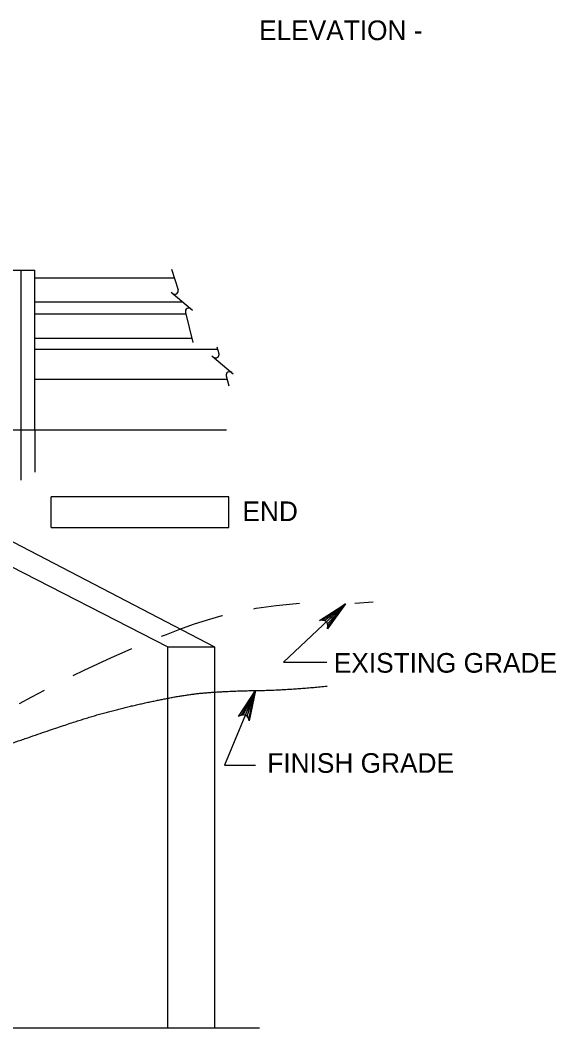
# Model space of a CAD drawing. Extents: x 638175 to 640495, y 294277 to 298435.
# Drawn here: x 638805.8 to 638887.6, y 297397.4 to 297551.4 of the extents above; entities that cross this region are included whole.
import ezdxf

# ---------------------------------------------------------------- set-up
doc = ezdxf.new("R2010")
doc.units = 0
for name, color, linetype in [('2', 7, 'Continuous'), ('3', 7, 'Continuous'), ('4', 7, 'Continuous'), ('8', 7, 'Continuous')]:
    doc.layers.add(name, color=color, linetype=linetype)

msp = doc.modelspace()

# ---------------------------------------------------------------- linework, layer by layer
at = {"layer": '2'}
for p, q in [((638829.33, 297512), (638808.04, 297512)), ((638830.65, 297508.31), (638808.04, 297508.31)), ((638831.1, 297506.46), (638808.04, 297506.46)), ((638832.02, 297502.76), (638808.04, 297502.76)), ((638835.95, 297501.1), (638808.04, 297501.1)), ((638837.4, 297496.48), (638808.04, 297496.48))]:
    msp.add_line(p, q, dxfattribs=at)
at = {"layer": '3'}
for p, q in [((638803.71, 297513.19), (638808.04, 297513.19)), ((638805.87, 297513.19), (638805.87, 297481.1)), ((638808.04, 297488.8), (638808.04, 297513.19)), ((638828.89, 297513.37), (638829.91, 297510.22)), ((638828.84, 297509.83), (638832.11, 297507.09)), ((638831.02, 297506.75), (638832.17, 297502.15)), ((638835.83, 297501.49), (638836.15, 297500.49)), ((638835.08, 297500.11), (638838.34, 297497.37)), ((638837.26, 297497.03), (638837.64, 297495.52)), ((638762.15, 297489.52), (638828.36, 297455.64)), ((638770.36, 297489.52), (638835.49, 297455.64)), ((638771.75, 297488.8), (638837.3, 297488.8)), ((638771.75, 297488.8), (638837.3, 297488.8)), ((638808.04, 297488.8), (638808.04, 297482.31)), ((638855.51, 297462.23), (638846.03, 297453.3)), ((638828.36, 297455.64), (638835.49, 297455.64)), ((638828.36, 297447.79), (638828.36, 297455.64)), ((638835.49, 297455.64), (638835.49, 297448.69)), ((638846.03, 297453.3), (638852.63, 297453.3)), ((638835.49, 297448.69), (638835.49, 297397.42)), ((638841.75, 297448.95), (638836.99, 297437.56)), ((638828.36, 297397.42), (638828.36, 297447.79)), ((638836.99, 297437.56), (638841.76, 297437.56)), ((638795.52, 297397.42), (638842.35, 297397.42))]:
    msp.add_line(p, q, dxfattribs=at)
for points in [[(638852.97, 297460.51), (638853.64, 297459.79), (638855.46, 297462.18)], [(638840.16, 297446.42), (638841.07, 297446.04), (638841.75, 297448.95)]]:
    msp.add_lwpolyline(points, close=True, dxfattribs=at)
for centre, start, end in [((638829.4, 297510.05), 227.8504, 17.8504), ((638831.55, 297506.87), 49.9832, 192.5218), ((638831.55, 297506.87), 49.9832, 49.9972), ((638835.64, 297500.33), 227.8504, 17.8504), ((638837.78, 297497.15), 49.9832, 192.5218), ((638837.79, 297497.14), 49.9832, 49.9972)]:
    msp.add_arc(centre, 0.533, start, end, dxfattribs=at)
msp.add_open_spline([(638803.01, 297440.4), (638810.78, 297443.09), (638817.93, 297445.42), (638825.08, 297447.16), (638831.83, 297448.47), (638838.18, 297448.91), (638846.72, 297449.05), (638852.67, 297449.64)], degree=2, dxfattribs=at)
at = {"layer": '4'}
for p, q in [((638837.64, 297478.57), (638810.49, 297478.57)), ((638810.49, 297473.87), (638810.49, 297478.57)), ((638837.64, 297473.87), (638837.64, 297478.57)), ((638810.49, 297473.87), (638837.64, 297473.87))]:
    msp.add_line(p, q, dxfattribs=at)
for points in [[(638855.51, 297462.23), (638852.72, 297458.4), (638852.81, 297458.83), (638852.73, 297459.18), (638852.56, 297459.45), (638852.3, 297459.64), (638851.95, 297459.74), (638851.52, 297459.67), (638855.51, 297462.23), (638851.95, 297459.74), (638852.3, 297459.64), (638855.51, 297462.23), (638852.56, 297459.45), (638852.73, 297459.18), (638855.51, 297462.23), (638852.81, 297458.83)], [(638841.75, 297448.95), (638840.76, 297444.31), (638840.67, 297444.74), (638840.45, 297445.03), (638840.18, 297445.2), (638839.87, 297445.27), (638839.52, 297445.22), (638839.15, 297444.99), (638841.75, 297448.95), (638839.52, 297445.22), (638839.87, 297445.27), (638841.75, 297448.95), (638840.18, 297445.2), (638840.45, 297445.03), (638841.75, 297448.95), (638840.67, 297444.74)]]:
    msp.add_lwpolyline(points, dxfattribs=at)
at = {"layer": '8'}
for p, q in [((638844.91, 297461.97), (638848.44, 297462.32)), ((638856.9, 297462.32), (638859.73, 297462.51)), ((638841.48, 297461.47), (638841.82, 297461.53)), ((638841.82, 297461.53), (638844.91, 297461.97)), ((638830.19, 297458.34), (638832.26, 297459.09)), ((638832.26, 297459.09), (638834.38, 297459.79)), ((638834.38, 297459.79), (638836.63, 297460.44)), ((638836.63, 297460.44), (638836.67, 297460.45)), ((638827.37, 297457.25), (638828.12, 297457.55)), ((638828.12, 297457.55), (638830.19, 297458.34)), ((638819.71, 297454.01), (638821.81, 297454.94)), ((638821.81, 297454.94), (638822.82, 297455.37)), ((638815.55, 297452.07), (638817.62, 297453.05)), ((638817.62, 297453.05), (638819.71, 297454.01)), ((638813.88, 297451.25), (638815.55, 297452.07)), ((638807.56, 297447.99), (638809.49, 297449.02)), ((638805.67, 297446.97), (638807.56, 297447.99))]:
    msp.add_line(p, q, dxfattribs=at)

# ---------------------------------------------------------------- texts
at = {"layer": '4'}
for s, p in [('   ELEVATION - ', (638838.94, 297548.36)), ('END', (638839.74, 297474.86)), ('EXISTING GRADE', (638853.7, 297451.69)), ('FINISH GRADE', (638843.54, 297436.39))]:
    msp.add_text(s, height=3, dxfattribs=at).set_placement(p)

doc.saveas('drawing.dxf')
